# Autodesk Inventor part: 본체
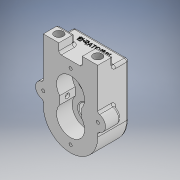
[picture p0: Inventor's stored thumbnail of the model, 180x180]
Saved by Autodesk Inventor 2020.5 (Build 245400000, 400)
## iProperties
Created: 2024-03
Part Number: 본체
Material: 일반
Document SubType Name: Modeling
Designer: 1강의실14
Density: 1 g/cm^3
Appearance: 기본값
Author: 1강의실14
## Parameters: d0 = 32 mm, d2 = 0, d3 = 33 mm, d7 = 35 mm, d9 = 0, d10 = 52 mm, d11 = 6 mm, d12 = 0, d13 = 12 mm, d16 = 0, d17 = 33 mm, d18 = 36 mm, d19 = 36 mm, d20 = 36 mm, d21 = 28 mm, d23 = 0, d25 = 63.5 mm, d27 = 0, d29 = 18 mm, d30 = 4 mm, d31 = 2 mm, d32 = 90 deg, d34 = 0, d35 = 14 mm, d37 = -60 deg, d38 = 15 mm, d39 = 18 mm, d40 = 4 mm, d41 = 2 mm, d42 = 90 deg, d44 = 0, d45 = 25 mm, d46 = 7.3 mm, d47 = 0, d48 = 15 mm, d49 = 63.5 mm, d50 = 8 mm, d51 = 6 mm, d52 = 0, d53 = 0, d54 = 10.5 mm, d55 = 11 mm, d56 = 0.62479 mm, d57 = 10.589 mm, d58 = 4 mm, d59 = 2 mm, d60 = 90 deg, d61 = 16 mm, d62 = 0, d63 = 30 deg, d64 = 0.7 mm, d65 = 90 deg, d66 = 26 mm, d67 = 26 mm, d68 = 4.134 mm, d70 = 4 mm, d71 = 2 mm, d72 = 90 deg, d73 = 12 mm, d74 = 118 deg, d75 = 42 mm, d76 = 3.242 mm, d77 = 8 mm, d78 = 4 mm, d79 = 2 mm, d80 = 90 deg, d82 = 118 deg, d84 = 360 deg, d86 = 3 mm, d87 = 3 mm, d88 = 3 mm, d92 = 1 mm, d93 = 2 mm, d94 = 45 deg, d96 = 0.5 mm, d97 = 0, d98 = 1 mm, d99 = 2 mm, d100 = 45 deg
